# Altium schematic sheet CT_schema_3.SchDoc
size 255 x 159 mm
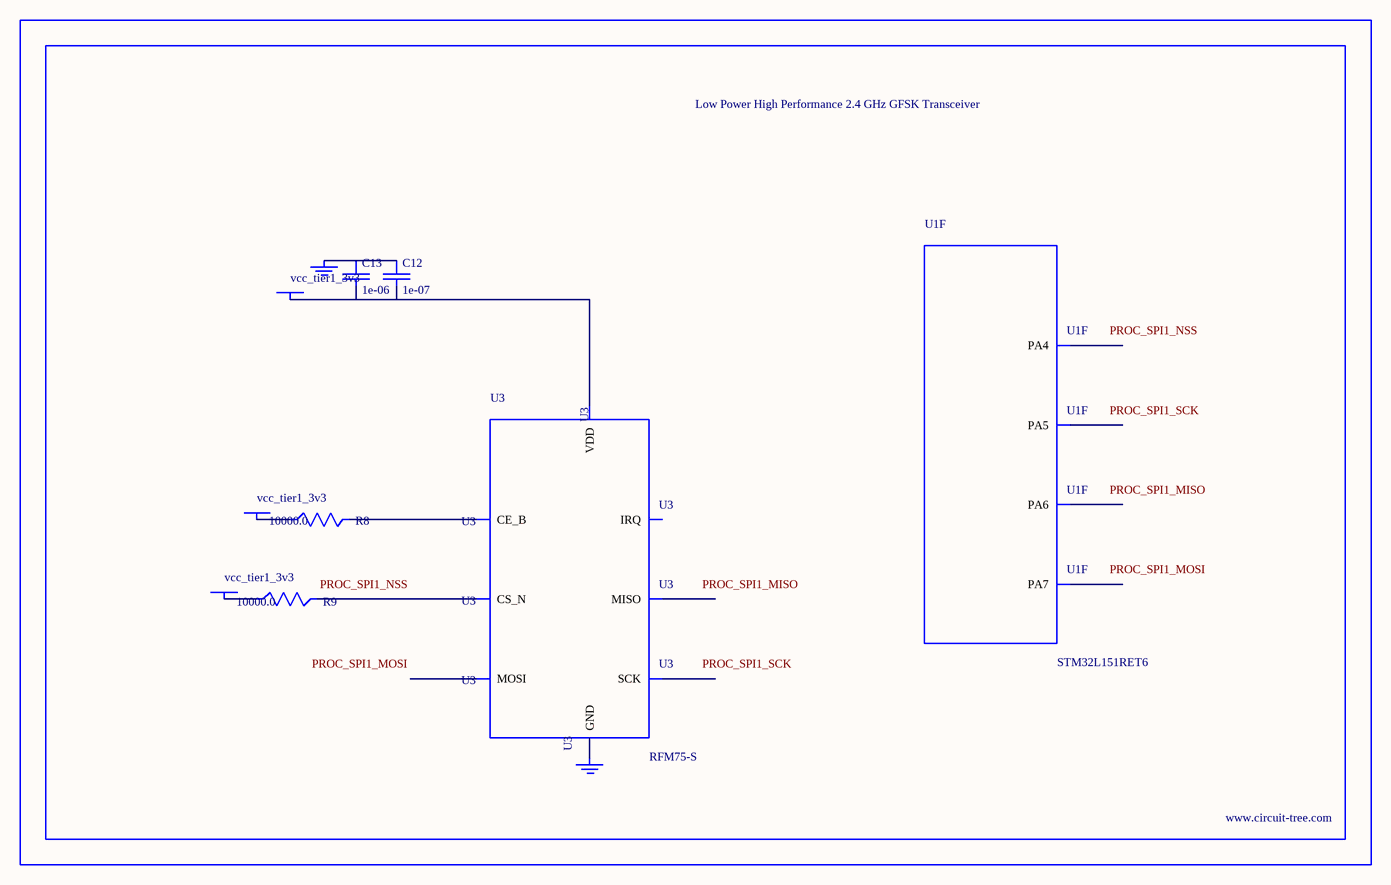
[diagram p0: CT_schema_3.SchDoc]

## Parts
BORDER2  (no value)
C12  1e-07  [C0402]
C13  1e-06  [C0603]
GND_INSTANCE_2_0  (no value)
GND_INSTANCE_2_1  (no value)
POWER_INSTANCE_2_0  vcc_tier1_3v3
POWER_INSTANCE_2_1  vcc_tier1_3v3
POWER_INSTANCE_2_2  vcc_tier1_3v3
R8  10000.0  [R0603]
R9  10000.0  [R0603]
U1  STM32L151RET6  [LQFP64]  (part F of 7)
U3  RFM75-S  [RFM75-S]

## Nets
NetC12_1: C12.1 C13.1 GND_INSTANCE_2_0.0(GND)
NetC12_2: C12.2 C13.2 POWER_INSTANCE_2_0.0(PWR) U3.2(VDD)
NetGND_INSTANCE_2_1_0: GND_INSTANCE_2_1.0(GND) U3.1(GND)
NetPOWER_INSTANCE_2_1_0: POWER_INSTANCE_2_1.0(PWR) R8.1
NetPOWER_INSTANCE_2_2_0: POWER_INSTANCE_2_2.0(PWR) R9.1
NetR8_2: R8.2 U3.3(CE_B)
NetR9_2: R9.2 U3.4(CS_N)

Not connected (* = marked no-connect by the designer): U1 20(PA4) 21(PA5) 22(PA6) 23(PA7); U3 5(SCK) 6(MOSI) 7(MISO) 8(IRQ)

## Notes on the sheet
- Labels drawn without touching a wire or pin: PROC_SPI1_MISO, PROC_SPI1_MOSI, PROC_SPI1_NSS, PROC_SPI1_SCK

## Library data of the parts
BORDER2 = BORDER_PAGE2
C12 = C0402C104K3RACTU
C13 = C0603C105K3RACTU
GND_INSTANCE_2_0 GND_INSTANCE_2_1 = GND
POWER_INSTANCE_2_0-POWER_INSTANCE_2_2 = PWR
R8 R9 = RC0603JR-0710KL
